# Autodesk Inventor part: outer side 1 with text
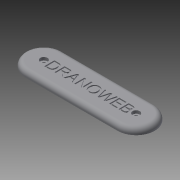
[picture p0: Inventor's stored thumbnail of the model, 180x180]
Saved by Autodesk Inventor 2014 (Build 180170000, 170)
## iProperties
Created: 2015-01
Part Number: outer side 1 with text
Material: Generic
Document SubType Name: Modeling
Designer: Drano
Density: 1 g/cm^3
Appearance: Default
Author: Drano
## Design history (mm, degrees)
sketch "Sketch1"
  geometry: L1 (-39.389, -16.629)-(37.611, -16.629); L2 (-39.389, 14.371)-(37.611, 14.371); C1 r 1.5 at (-39.389, -1.129); C2 r 1.5 at (37.611, -1.129); A1 r 15.5 centre (37.611, -1.129) between (37.611, -16.629) and (37.611, 14.371); A2 r 15.5 centre (-39.389, -1.129) between (-39.389, 14.371) and (-39.389, -16.629); 1 further point
  constraints: 4 centre point, 4 end point, 4 point on circle
extrude "Extrusion1" new body sketch "Sketch1" distance "d0" = 5; taper "d1" = 0 deg
fillet "Fillet1" dims "d2" = 4
feature "Lip1" dims "d3" = 2.5, "d4" = 1.5, "d5" = 0, "d6" = 0, "d7" = 0, "d8" = 0
feature "Lip2" dims "d9" = 2.5, "d10" = 1.5, "d11" = 0, "d12" = 0, "d13" = 0, "d14" = 0
sketch "Sketch2"
  geometry: L1 (-35.605, 3.109)-(31.041, 3.109); L2 (31.041, 3.109)-(31.041, -12.449); L3 (31.041, -12.449)-(-35.605, -12.449); L4 (-35.605, -12.449)-(-35.605, 3.109); 1 further point
  constraints: 2 other
emboss "Emboss1" sketch "Sketch2" dims "d15" = 1, "d16" = 0
body "Solid1"
